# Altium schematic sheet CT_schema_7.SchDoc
size 278 x 170 mm
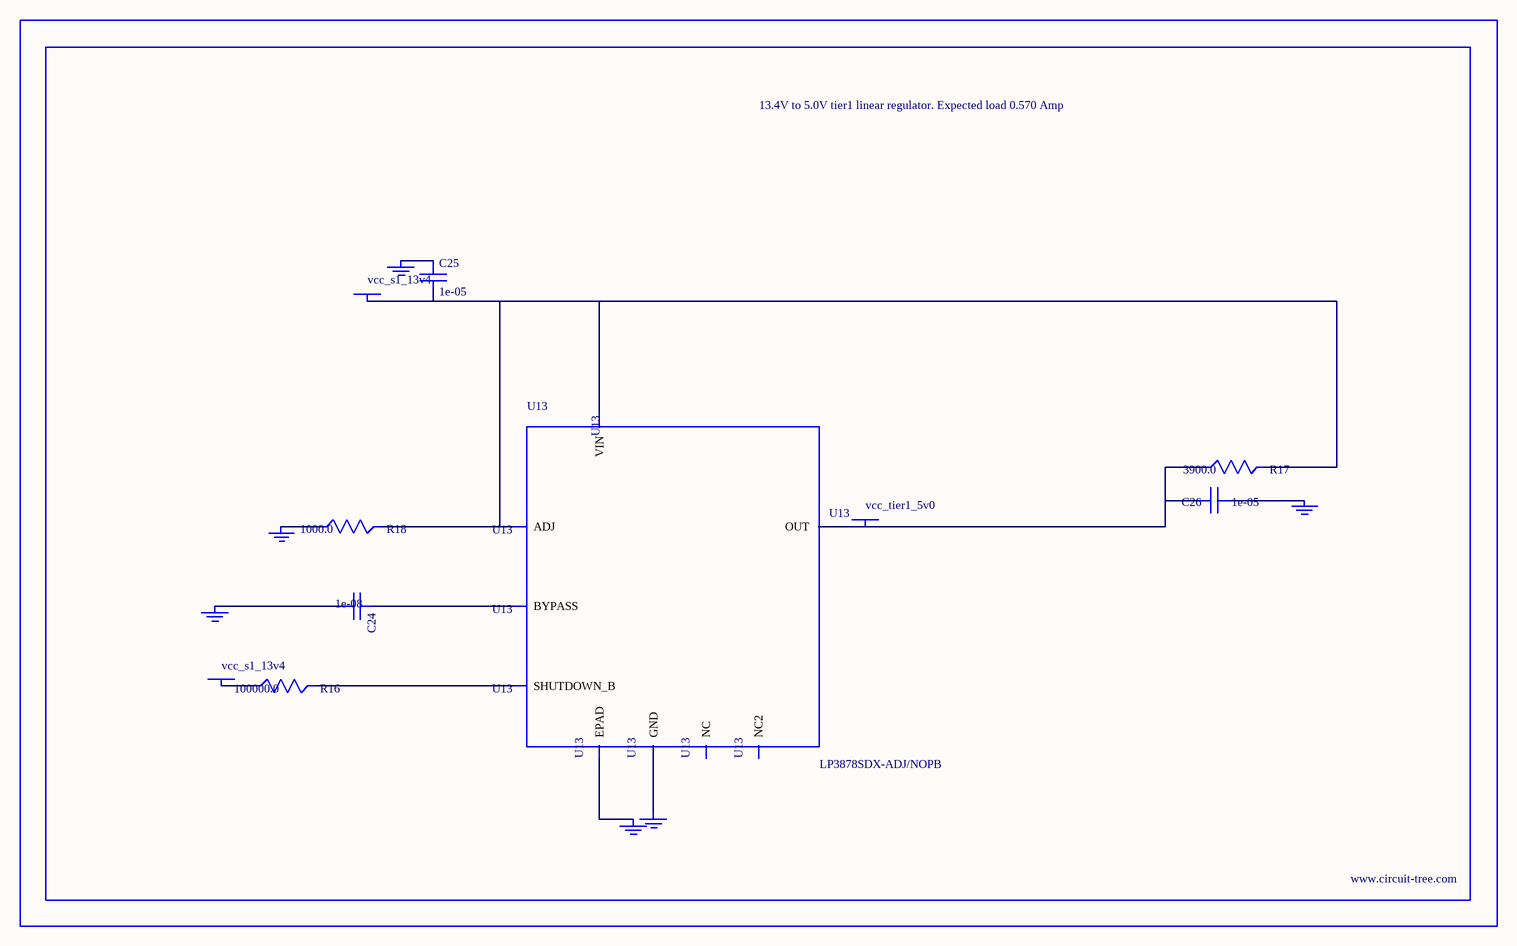
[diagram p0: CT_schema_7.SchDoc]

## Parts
BORDER6  (no value)
C24  1e-08  [C0402]
C25  1e-05  [C1210]
C26  1e-05  [C1210]
GND_INSTANCE_6_0  (no value)
GND_INSTANCE_6_1  (no value)
GND_INSTANCE_6_2  (no value)
GND_INSTANCE_6_3  (no value)
GND_INSTANCE_6_4  (no value)
GND_INSTANCE_6_5  (no value)
POWER_INSTANCE_6_0  vcc_s1_13v4
POWER_INSTANCE_6_1  vcc_s1_13v4
POWER_INSTANCE_6_2  vcc_tier1_5v0
R16  100000.0  [R0603]
R17  3900.0  [R0603]
R18  1000.0  [R0603]
U13  LP3878SDX-ADJ/NOPB  [WSON-8]

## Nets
NetC24_1: C24.1 U13.1(BYPASS)
NetC24_2: C24.2 GND_INSTANCE_6_0.0(GND)
NetC25_1: C25.1 GND_INSTANCE_6_1.0(GND)
NetC25_2: C25.2 POWER_INSTANCE_6_0.0(PWR) R17.2 R18.2 U13.4(VIN) U13.6(ADJ)
NetC26_1: C26.1 GND_INSTANCE_6_2.0(GND)
NetC26_2: C26.2 POWER_INSTANCE_6_2.0(PWR) R17.1 U13.5(OUT)
NetGND_INSTANCE_6_3_0: GND_INSTANCE_6_3.0(GND) R18.1
NetGND_INSTANCE_6_4_0: GND_INSTANCE_6_4.0(GND) U13.PAD(EPAD)
NetGND_INSTANCE_6_5_0: GND_INSTANCE_6_5.0(GND) U13.3(GND)
NetPOWER_INSTANCE_6_1_0: POWER_INSTANCE_6_1.0(PWR) R16.1
NetR16_2: R16.2 U13.8(SHUTDOWN_B)

Not connected (* = marked no-connect by the designer): U13 2(NC) 7(NC2)

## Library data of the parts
BORDER6 = BORDER_PAGE6
C24 = C0402C103K3RAC
C25 = C1210C106K5PACTU
C26 = GRM32DR61E106MA12L
GND_INSTANCE_6_0-GND_INSTANCE_6_5 = GND
POWER_INSTANCE_6_0-POWER_INSTANCE_6_2 = PWR
R16 = RC0603JR-07100KL
R17 = RC0603JR-073K9L
R18 = RC0603JR-071KL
